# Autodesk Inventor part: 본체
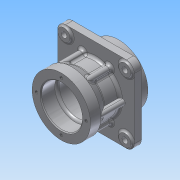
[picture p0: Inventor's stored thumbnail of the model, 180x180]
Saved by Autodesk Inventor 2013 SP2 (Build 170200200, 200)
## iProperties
Created: 2025-08
Part Number: 본체
Material: 알루미늄 6061
Document SubType Name: Modeling
Designer: i
Density: 2.71 g/cm^3
Author: i
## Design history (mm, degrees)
sketch "스케치1"
  geometry: L1 (-35, 44)-(35, 44); L2 (44, 35)-(44, -35); L3 (35, -44)-(-35, -44); L4 (-44, -35)-(-44, 35); L5 (-50.045, 0)-(59.505, 0); L6 (0, 93.552)-(0, -130.317); A1 r 9 centre (-35, 35) between (-35, 44) and (-44, 35); A2 r 9 centre (35, 35) between (44, 35) and (35, 44); A3 r 9 centre (35, -35) between (35, -44) and (44, -35); A4 r 9 centre (-35, -35) between (-44, -35) and (-35, -44); 4 further points
  constraints: 12 end point, 8 point on circle, 8 point on line, 8 tangent, 4 centre point, 3 perpendicular, 2 equal radius, 2 parallel, 1 horizontal, 2 other
  dimensions: "d0" = 88 distance of point (44, 44) point (44, -44); "d2" = 88 distance of point (-44, 44) point (44, 44); "d3" = 9 radius of A1; "d4" = 9 radius of A2
extrude "돌출1" new body sketch "스케치1" distance "d5" = 8; taper "d6" = 0 deg
sketch "스케치2"
  geometry: C1 r 7 at (-35, 35); C2 r 7 at (35, 35); C3 r 7 at (-35, -35); C4 r 7 at (35, -35); A1 r 9 centre (35, -35) between (35, -44) and (44, -35) reference; A2 r 9 centre (35, 35) between (44, 35) and (35, 44) reference; A3 r 9 centre (-35, 35) between (-35, 44) and (-44, 35) reference; A4 r 9 centre (-35, -35) between (-44, -35) and (-35, -44) reference; 1 further point
  constraints: 4 centre point, 4 coincident
  dimensions: "d8" = 14 diameter of C1; "d9" = 14 diameter of C2; "d10" = 14 diameter of C3; "d11" = 14 diameter of C4
extrude "돌출2" join sketch "스케치2" distance "d12" = 10; taper "d13" = 0 deg
sketch "스케치3"
  geometry: C1 r 3.3 at (-35, 35); C2 r 3.3 at (35, 35); C3 r 3.3 at (-35, -35); C4 r 3.3 at (35, -35); A1 r 9 centre (35, -35) between (35, -44) and (44, -35) reference; A2 r 9 centre (35, 35) between (44, 35) and (35, 44) reference; A3 r 9 centre (-35, 35) between (-35, 44) and (-44, 35) reference; A4 r 9 centre (-35, -35) between (-44, -35) and (-35, -44) reference; 1 further point
  constraints: 4 centre point, 4 coincident
  dimensions: "d14" = 6.6 diameter of C1; "d15" = 6.6 diameter of C2; "d16" = 6.6 diameter of C3; "d17" = 6.6 diameter of C4
extrude "돌출3" cut sketch "스케치3" distance "d18" = 10; taper "d19" = 0 deg
sketch "스케치5"
  geometry: L1 (-35, -44)-(35, -44) reference; L2 (44, -35)-(44, 35) reference; L3 (35, 44)-(-35, 44) reference; L4 (-44, 35)-(-44, -35) reference; C1 r 3.3 at (-35, -35) reference; C2 r 3.3 at (-35, 35) reference; C3 r 3.3 at (35, 35) reference; C4 r 3.3 at (35, -35) reference; A1 r 9 centre (35, -35) between (35, -44) and (44, -35) reference; A2 r 9 centre (35, 35) between (44, 35) and (35, 44) reference; A3 r 9 centre (-35, 35) between (-35, 44) and (-44, 35) reference; A4 r 9 centre (-35, -35) between (-44, -35) and (-35, -44) reference; 1 further point
sketch "스케치7"
  geometry: C1 r 38.5 at (0, 0); 1 further point
  constraints: 1 centre point, 1 coincident
  dimensions: "d31" = 77 diameter of C1
extrude "돌출4" join sketch "스케치7" distance "d32" = 5; taper "d33" = 0 deg
sketch "스케치8"
  geometry: C1 r 38.5 at (0, 0) reference; C2 r 33.5 at (0, 0)
  constraints: 1 centre point, 1 coincident
  dimensions: "d34" = 67 diameter of C2
extrude "돌출5" join sketch "스케치8" distance "d35" = 13; taper "d36" = 0 deg
sketch "스케치12"
  geometry: L1 (0, 27.5)-(-18, 27.5); L2 (-40, 33.5)-(-40, 0); L3 (-40, 33.5)-(-28, 33.5); L4 (-28, 33.5)-(-18, 27.5); L5 (0, 27.5)-(0, 0); L6 (-1.03, 0)-(-60.593, 0); L7 (-40, 0)-(0, 0)
  constraints: 14 end point, 4 perpendicular, 1 horizontal, 1 point on line
  dimensions: "d43" = 18 distance of L1.start L1.end; "d44" = 33.5 distance of L2.start L2.end; "d45" = 12 distance of L2.start L3.end; "d46" = 10 horizontal distance of L3.end L1.end; "d47" = 67 diameter of L3 L6; "d48" = 55 diameter of L1 L6
revolve "회전1" sketch "스케치12" stored, may be unused: angle "d49" = 90 deg
sketch "스케치14"
  geometry: L1 (44, -35)-(44, 35) reference; L2 (30.5, 3)-(27.336, 3); L3 (30.5, -3)-(27.336, -3); L4 (-53.127, 0)-(53.127, 0); L5 (12.652, 27.914)-(11.07, 25.174); L6 (17.848, 24.914)-(16.266, 22.174); L7 (-17.848, 24.914)-(-16.266, 22.174); L8 (-12.652, 27.914)-(-11.07, 25.174); L9 (-30.5, -3)-(-27.336, -3); L10 (-30.5, 3)-(-27.336, 3); L11 (-12.652, -27.914)-(-11.07, -25.174); L12 (-17.848, -24.914)-(-16.266, -22.174); L13 (17.848, -24.914)-(16.266, -22.174); L14 (12.652, -27.914)-(11.07, -25.174); C1 r 33.5 at (0, 0) reference; A1 r 27.5 centre (0, 0) between (27.336, 3) and (27.336, -3) reference; A2 r 3 centre (30.5, 0) between (30.5, -3) and (30.5, 3); A3 r 3 centre (15.25, 26.414) between (17.848, 24.914) and (12.652, 27.914); A4 r 3 centre (-15.25, 26.414) between (-12.652, 27.914) and (-17.848, 24.914); A5 r 3 centre (-30.5, 0) between (-30.5, 3) and (-30.5, -3); A6 r 3 centre (-15.25, -26.414) between (-17.848, -24.914) and (-12.652, -27.914); A7 r 3 centre (15.25, -26.414) between (12.652, -27.914) and (17.848, -24.914); 1 further point
  constraints: 26 end point, 14 point on circle, 6 centre point, 3 tangent, 2 parallel, 1 coincident, 1 midpoint, 1 perpendicular, 1 point on line, 49 other
  dimensions: "d59" = 6 diameter of A2; "d63" = 360 deg dimension on C1.centre L2.start (derived)
extrude "돌출8" join sketch "스케치14" distance "d65" = 30; taper "d66" = 0 deg
sketch "스케치15"
  geometry: L1 (-51.297, 0)-(39.522, 0); L2 (-40, -33.5)-(-40, 33.5) reference; L3 (-40, 0)-(-40, 23.5); L4 (-40, 23.5)-(-24, 23.5); L5 (-24, 23.5)-(-24, 21); L6 (26, -33.5)-(26, 33.5) reference; L7 (26, 0)-(26, 23.5); L8 (26, 23.5)-(10, 23.5); L9 (10, 23.5)-(10, 21); L10 (10, 21)-(-24, 21); L11 (-40, 0)-(26, 0); 1 further point
  constraints: 18 end point, 5 perpendicular, 4 point on line, 2 midpoint, 1 horizontal, 1 parallel
  dimensions: "d70" = 23.5 distance of L3.start L3.end; "d72" = 16 distance of L3.end L4.end; "d73" = 16 distance of L7.end L8.end; "d74" = 42 diameter of L10 L1; "d75" = 47 diameter of L8 L1
revolve "회전2" sketch "스케치15" stored, may be unused: angle "d76" = 90 deg
sketch "스케치16"
  geometry: L1 (0, 0)-(0, 50.717); C1 r 23.5 at (0, 0) reference; C2 r 33.5 at (0, 0) reference; C3 r 2 at (0, 28.5)
  constraints: 2 end point, 1 centre point, 1 point on line, 1 vertical
  dimensions: "d77" = 4 diameter of C3; "d78" = 28.5 distance of C1.centre C3.centre
hole "구멍1" sketch "스케치16" at (0, 28.5) diameter "d79" = 3.242; stored, may be unused: countersink angle "d83" = 90 deg, drill point angle "d85" = 118 deg; dims "d80" = 8, "d81" = 4, "d82" = 2, "d84" = 10
sketch "스케치17"
  geometry: L1 (0, 0)-(0, 55.993); C1 r 23.5 at (0, 0) reference; C2 r 33.5 at (0, 0) reference; C3 r 2 at (0, 28.5)
  constraints: 2 end point, 1 centre point, 1 point on line, 1 vertical
  dimensions: "d89" = 4 diameter of C3; "d91" = 28.5 distance of C1.centre C3.centre
hole "구멍2" sketch "스케치17" at (0, 28.5) diameter "d92" = 3.242; stored, may be unused: countersink angle "d96" = 90 deg, drill point angle "d98" = 118 deg; dims "d93" = 8, "d94" = 4, "d95" = 2, "d97" = 10
fillet "모깎기1" dims "d102" = 3
fillet "모깎기2" dims "d103" = 3
fillet "모깎기3" dims "d104" = 3
fillet "모깎기4" dims "d105" = 3
chamfer "모따기1" distance "d106" = 1; stored, may be unused: second distance "d107" = 2, angle "d108" = 45 deg
chamfer "모따기2" distance "d109" = 1; stored, may be unused: second distance "d110" = 2, angle "d111" = 45 deg
fillet "모깎기5" dims "d112" = 0.6
node "솔리드1"
pattern_circular "원형 패턴1" dims angle "d68" = 360 deg
pattern_circular "원형 패턴2" dims angle "d87" = 360 deg
pattern_circular "원형 패턴3" dims angle "d100" = 360 deg
